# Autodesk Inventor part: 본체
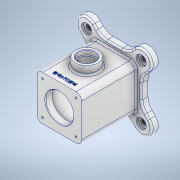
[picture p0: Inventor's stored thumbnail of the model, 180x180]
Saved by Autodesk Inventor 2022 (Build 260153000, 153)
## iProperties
Created: 2022-05
Part Number: 본체
Material: 알루미늄 6061
Document SubType Name: Modeling
Designer: admin
Mass: 1076.28 g
Surface Area: 879.96 cm^2
Volume: 398.62 cm^3
Density: 2.7 g/cm^3
Appearance: 알루미늄 - 평지
Author: admin
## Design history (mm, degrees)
sketch "스케치1"
  geometry: L1 (-40, 40)-(40, 40); L2 (40, 40)-(40, -40); L3 (40, -40)-(-40, -40); L4 (-40, -40)-(-40, 40); L5 (-40, 40)-(40, -40); L6 (40, 40)-(-40, -40); 1 further point
  constraints: 12 end point, 2 midpoint, 2 parallel, 1 horizontal, 1 perpendicular
  dimensions: "d0" = 80 distance of L1.start L1.end; "d1" = 80 distance of L1.end L2.end
extrude "돌출1" new body sketch "스케치1" stored distance "d2" = 98; taper "d3" = 0 deg
sketch "스케치2"
  geometry: L1 (49, 49)-(-49, 49); L2 (-49, 49)-(-49, -49); L3 (-49, -49)-(49, -49); L4 (49, -49)-(49, 49); L5 (49, 49)-(-49, -49); L6 (-49, 49)-(49, -49); 1 further point
  constraints: 12 end point, 2 midpoint, 2 parallel, 1 horizontal, 1 perpendicular
  dimensions: "d4" = 98 distance of L3.end L1.start; "d5" = 98 distance of L2.end L3.end
extrude "돌출2" join sketch "스케치2" distance "d6" = 12; taper "d7" = 0 deg
sketch "스케치3" dims "d71" = 140
  geometry: L1 (0, 0)-(71.621, 71.621); L2 (-98, 0)-(98, 0) reference; L3 (36.77, 62.225)-(-62.225, -36.77); L4 (62.225, 36.77)-(-36.77, -62.225); L5 (-36.77, 62.225)-(62.225, -36.77); L6 (-62.225, 36.77)-(36.77, -62.225); A1 r 18 centre (49.497, 49.497) between (36.77, 62.225) and (62.225, 36.77); A2 r 18 centre (-49.497, 49.497) between (-62.225, 36.77) and (-36.77, 62.225); A3 r 18 centre (-49.497, -49.497) between (-36.77, -62.225) and (-62.225, -36.77); A4 r 18 centre (49.497, -49.497) between (62.225, -36.77) and (36.77, -62.225); 6 further points
  constraints: 10 end point, 8 point on circle, 8 tangent, 4 centre point, 1 coincident, 1 point on line, 12 other
  dimensions: "d72" = 45 deg angle of L2 L1; "d73" = 36 diameter of A1; "d76" = 360 deg dimension on point (0, 0) A1.centre (derived)
extrude "돌출3" join sketch "스케치3" distance "d10" = 12; taper "d11" = 0 deg
sketch "스케치4"
  geometry: A1 r 18 centre (-49, 49) between (-36.272, 61.728) and (-61.728, 36.272) reference; 2 further points
  constraints: 1 coincident
hole "구멍1" sketch "스케치4" at (-49, 49) diameter "d12" = 10; stored, may be unused: countersink angle "d16" = 90 deg, drill point angle "d18" = 0 deg; dims "d13" = 8, "d14" = 18, "d15" = 4, "d17" = 12
sketch "스케치5"
  geometry: L1 (25, 49)-(25, 37); L2 (25, 37)-(32, 37); L3 (35, 34)-(35, -46); L4 (32, -49)-(25, -49); L5 (25, -49)-(25, -61); L6 (-49, -61)-(49, -61) reference; L7 (40, 49)-(-40, 49) reference; L8 (0, -83)-(0, 71) reference; L9 (25, 49)-(0, 49); L10 (0, 49)-(0, -61); L11 (0, -61)-(25, -61); L12 (23.544, -49)-(23.544, -61) reference; A1 r 3 centre (32, 34) between (35, 34) and (32, 37); A2 r 3 centre (32, -46) between (32, -49) and (35, -46); 3 further points
  constraints: 16 end point, 6 point on line, 4 perpendicular, 4 point on circle, 4 tangent, 2 centre point, 2 midpoint, 1 equal radius, 1 vertical
  dimensions: "d22" = 50 diameter of L1 L8; "d23" = 70 diameter of L3 L8; "d24" = 12 distance of L1.start L1.end; "d25" = 12 distance of L4.end L5.end; "d26" = 3 radius of A1
revolve "회전1" sketch "스케치5" stored, may be unused: angle "d27" = 90 deg
node "작업 평면1"
sketch "스케치6"
  geometry: C1 r 20 at (0, 0); 1 further point
  constraints: 1 centre point, 1 coincident
  dimensions: "d29" = 40 diameter of C1
extrude "돌출4" join sketch "스케치6" stored distance "d30" = 12; taper "d31" = 0 deg
sketch "스케치7"
  geometry: C1 r 15 at (0, 0); 1 further point
  constraints: 1 centre point, 1 coincident
  dimensions: "d32" = 30 diameter of C1
extrude "돌출5" cut sketch "스케치7" distance "d33" = 8; taper "d34" = 0 deg
sketch "스케치8"
  geometry: C1 r 12.5 at (0, 0); 1 further point
  constraints: 1 centre point, 1 coincident
  dimensions: "d35" = 25 diameter of C1
extrude "돌출6" cut sketch "스케치8" stored distance "d36" = 8; taper "d37" = 0 deg
sketch "스케치9"
  geometry: L1 (-40, 40)-(-40, -40) reference; L2 (40, 40)-(-40, 40) reference; 2 further points
  dimensions: "d38" = 10 distance from line of L1 point (-30, 30); "d39" = 10 distance from line of L2 point (-30, 30)
hole "구멍2" sketch "스케치9" at (-30, 30) diameter "d40" = 3.242; stored, may be unused: countersink angle "d44" = 90 deg, drill point angle "d46" = 118 deg; dims "d41" = 8, "d42" = 18, "d43" = 4, "d45" = 10
sketch "스케치10"
  geometry: L1 (-30, 30)-(30, 30); L2 (30, 30)-(30, -30); L3 (30, -30)-(-30, -30); L4 (-30, -30)-(-30, 30); L5 (-30, 30)-(30, -30); L6 (30, 30)-(-30, -30); C1 r 1.621 at (-30, -30) reference; 2 further points
  constraints: 12 end point, 2 midpoint, 2 parallel, 1 coincident, 1 horizontal, 1 perpendicular
  dimensions: "d50" = 60 distance of L1.end L2.end; "d51" = 60 distance of L2.end L3.end
hole "구멍3" sketch "스케치10" at (-30, -30) diameter "d52" = 3.242; stored, may be unused: countersink angle "d56" = 90 deg, drill point angle "d58" = 118 deg; dims "d53" = 8, "d54" = 4, "d55" = 2, "d57" = 10
fillet "모깎기2" dims "d63" = 10
chamfer "모따기1" distance "d65" = 1; stored, may be unused: second distance "d66" = 2, angle "d67" = 45 deg
sketch "스케치11" dims "d0" = 80, "d1" = 80
  geometry: L1 (60, 0)-(0, 0) reference; L2 (30, 132)-(30, -22) reference; 2 further points
  constraints: 1 point on line, 1 other
  dimensions: "d68" = 10 distance from line of L1 point (30, 10)
feature "엠보싱1" sketch "스케치11" dims "d0" = 80, "d1" = 80, "d69" = 0.5, "d70" = 0
fillet "모깎기4" dims "d78" = 25
fillet "모깎기5" dims "d79" = 3
node "솔리드1"
pattern_circular "원형 패턴1" dims angle "d20" = 360 deg
pattern_circular "원형 패턴2" dims angle "d48" = 360 deg
pattern_circular "원형 패턴3" dims angle "d60" = 360 deg
feature "A9D066F2-1C7D-4E18-AEED-F7BC21143FA4" dims "d12" = 10, "d13" = 8, "d14" = 18, "d15" = 4, "d16" = 90 deg, "d17" = 12, "d18" = 0
other parameters: "d28" = 55
